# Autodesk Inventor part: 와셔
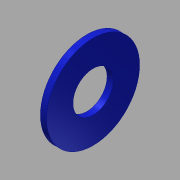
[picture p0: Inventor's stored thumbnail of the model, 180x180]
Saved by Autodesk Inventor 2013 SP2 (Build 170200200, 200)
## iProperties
Created: 2015-12
Part Number: 와셔
Material: 스테인리스강
Document SubType Name: Modeling
Designer: mduedu
Density: 8.08 g/cm^3
Author: mduedu
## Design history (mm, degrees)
sketch "스케치1"
  geometry: C1 r 3.25 at (0, 0); C2 r 7.5 at (0, 0); 1 further point
  constraints: 2 centre point, 2 coincident
  dimensions: "d0" = 6.5 diameter of C1; "d1" = 15 diameter of C2
extrude "돌출1" new body sketch "스케치1" stored distance "d2" = 1; taper "d3" = 0 deg
node "솔리드1"
